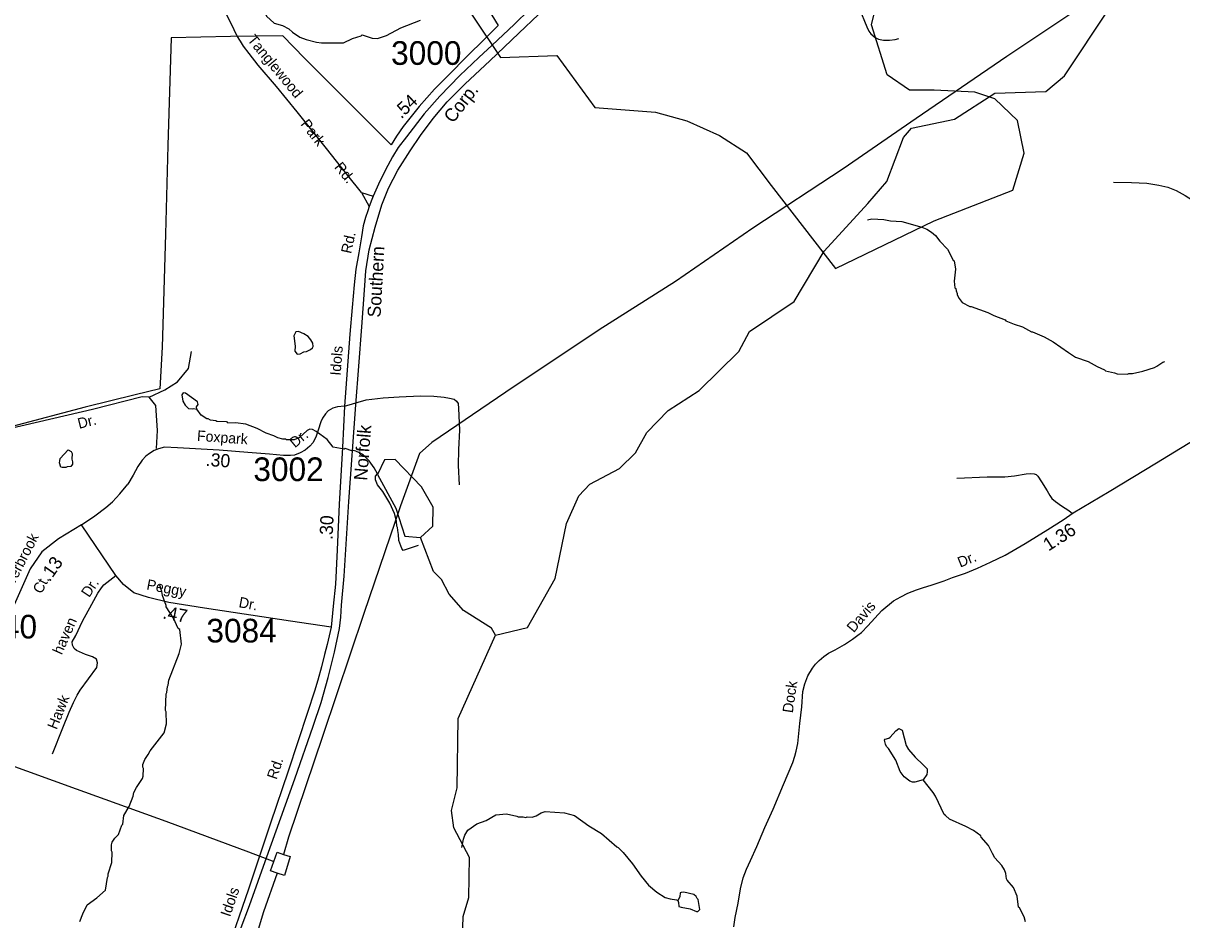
# Model space of a CAD drawing. Extents: x 1551653 to 1702041, y 811336 to 920032.
# Drawn here: x 1584838 to 1592068, y 814553 to 820151 of the extents above; entities that cross this region are included whole.
import ezdxf

# ---------------------------------------------------------------- set-up
doc = ezdxf.new("R2010")
doc.units = 0
for name, color, linetype in [('Old_Level_10', 7, 'Continuous'), ('Old_Level_11', 7, 'Continuous'), ('Old_Level_14', 7, 'Continuous'), ('Old_Level_17', 7, 'Continuous'), ('Old_Level_32', 7, 'Continuous'), ('Old_Level_35', 7, 'Continuous'), ('Old_Level_44', 7, 'Continuous'), ('Old_Level_48', 7, 'Continuous'), ('Old_Level_49', 7, 'Continuous'), ('Old_Level_53', 7, 'Continuous'), ('Old_Level_56', 7, 'Continuous'), ('Old_Level_59', 7, 'Continuous'), ('Old_Level_60', 7, 'Continuous'), ('Old_Level_62', 7, 'Continuous'), ('Old_Level_8', 7, 'Continuous')]:
    doc.layers.add(name, color=color, linetype=linetype)

msp = doc.modelspace()

# ---------------------------------------------------------------- linework, layer by layer
at = {"layer": 'Old_Level_32'}
for points in [[(1588000.194, 820239.075), (1587900.745, 820142.609), (1587764.879, 820014.729), (1587681.559, 819936.307), (1587563.41, 819824.135), (1587437.39, 819696.042), (1587339.631, 819585.756), (1587229.372, 819441.583), (1587178.112, 819374.343), (1587141.508, 819317.312), (1587099.805, 819235.764), (1587054.34, 819146.41), (1587021.295, 819070.925), (1587013.021, 819051.397), (1586996.374, 819007.418), (1586987.929, 818979.36), (1586973.296, 818937.638), (1586960.432, 818886.033), (1586949.212, 818818.31), (1586931.436, 818718.55), (1586913.907, 818614.846), (1586902.404, 818516.93), (1586890.048, 818377.012), (1586877.129, 818209.204), (1586859.799, 817985.681), (1586842.093, 817759.868)], [(1586842.093, 817759.868), (1586800.013, 817756.78), (1586769.947, 817747.213), (1586741.725, 817731.374), (1586723.609, 817712.043), (1586704.701, 817686.167), (1586694.373, 817662.41), (1586679.534, 817610.518), (1586664.862, 817566.83), (1586644.445, 817531.134), (1586626.286, 817509.835), (1586597.575, 817486.128), (1586567.346, 817468.356), (1586530.965, 817454.98), (1586504.964, 817451.564), (1586462.307, 817452.431), (1586375.141, 817459.776), (1586239.482, 817471.715), (1586061.5, 817484.511), (1585801.852, 817500.931), (1585719.854, 817504.232), (1585681.586, 817494.832), (1585655.418, 817483.215), (1585625.195, 817465.774), (1585603.151, 817447.181), (1585580.337, 817422.693), (1585553.932, 817383.182), (1585524.936, 817329.278), (1585490.009, 817274.18)], [(1586842.093, 817759.868), (1586829.976, 817502.099), (1586810.013, 817148.639), (1586797.66, 816862.973), (1586786.102, 816648.856), (1586771.824, 816511.274), (1586758.874, 816379.902)], [(1589272.456, 814509.499), (1589281.187, 814567.158), (1589298.649, 814658.014), (1589313.141, 814747.823), (1589330.602, 814815.965), (1589351.556, 814870.129), (1589376.002, 814924.293), (1589416.164, 815011.655), (1589466.803, 815130.468), (1589517.441, 815244.038), (1589582.049, 815397.447), (1589639.672, 815535.478), (1589653.641, 815575.664), (1589660.626, 815607.114), (1589671.103, 815654.29), (1589685.072, 815780.091), (1589697.295, 815883.178), (1589702.534, 815979.276), (1589714.978, 816025.949), (1589735.181, 816076.487), (1589762.599, 816124.136), (1589781.358, 816148.683), (1589804.446, 816173.23), (1589834.751, 816197.777), (1589863.611, 816217.992), (1589904.016, 816239.651), (1589963.181, 816272.862), (1590012.245, 816304.629), (1590046.879, 816330.619), (1590068.524, 816347.946), (1590108.929, 816388.377), (1590195.512, 816485.12), (1590269.108, 816544.321), (1590313.842, 816568.869), (1590358.577, 816593.416), (1590412.708, 816614.583), (1590448.656, 816625.374), (1590509.768, 816645.158), (1590585.259, 816670.337), (1590637.384, 816690.121), (1590718.268, 816717.099), (1590792.501, 816749.472), (1590874.643, 816787.241), (1590966.31, 816830.405), (1591090.332, 816902.346), (1591232.327, 816990.474), (1591327.59, 817051.623), (1591390.5, 817094.788), (1591614.457, 817228.418), (1591909.231, 817406.471), (1592220.184, 817595.316)], [(1585202.024, 817019.055), (1585058.115, 816932.179), (1584955.323, 816849.875), (1584882.227, 816744.71), (1584749.169, 816445.787)], [(1586758.874, 816379.902), (1586505.321, 816418.769), (1585968.519, 816498.786), (1585747.6, 816535.019), (1585619.681, 816564.74), (1585528.311, 816594.461), (1585464.352, 816647.044), (1585416.662, 816703.125), (1585202.024, 817019.055)], [(1586758.874, 816379.902), (1586733.818, 816271.757), (1586718.779, 816210.022), (1586699.809, 816132.279), (1586676.122, 816048.723), (1586655.052, 815980.872), (1586612.966, 815847.795), (1586490.984, 815481.627), (1586381.674, 815157.55), (1586243.016, 814745.766), (1586104.482, 814340.216), (1586122.37, 814330.733)]]:
    msp.add_lwpolyline(points, dxfattribs=at)
at = {"layer": 'Old_Level_35'}
for q in [(1586996.374, 819007.418), (1587021.295, 819070.925)]:
    msp.add_line((1586949.546, 819094.041), q, dxfattribs=at)
for points in [[(1589878.1, 820706.23), (1589973.779, 820454.813), (1590054.553, 820245.388), (1590102.739, 820128.537), (1590115.318, 820101.362), (1590127.453, 820084.705), (1590153.579, 820061.854), (1590175.363, 820051.566), (1590205.432, 820045.047), (1590243.493, 820044.276), (1590279.386, 820049.788), (1590301.489, 820055.247)], [(1586949.546, 819094.041), (1586863.385, 819199.517), (1586729.947, 819369.635), (1586547.812, 819598.837), (1586418.396, 819756.727), (1586304.538, 819888.695), (1586247.917, 819961.733), (1586212.419, 820008.078), (1586194.984, 820038.633), (1586171.756, 820074.883), (1586138.718, 820145.473), (1586090.044, 820238.045), (1586053.364, 820307.064), (1586014.174, 820365.633), (1585977.124, 820416.28), (1585937.527, 820454.829), (1585882.344, 820501.578), (1585838.725, 820535.941), (1585787.574, 820571.119), (1585740.946, 820602.92), (1585692.482, 820624.911), (1585652.653, 820635.564), (1585612.735, 820641.952), (1585558.791, 820652.893)], [(1591641.01, 819159.533), (1591754.875, 819157.555), (1591848.972, 819152.04), (1591924.576, 819140.987), (1591980.445, 819128.037), (1592032.217, 819107.296), (1592087.722, 819076.299), (1592135.35, 819045.462), (1592172.846, 819016.801), (1592208.381, 818988.507), (1592241.475, 818953.041), (1592260.294, 818926.069), (1592286.462, 818889.104), (1592323.965, 818828.271), (1592405.749, 818701.221), (1592516.789, 818527.291), (1592635.749, 818339.414), (1592780.266, 818116.878), (1592844.385, 818014.772)], [(1585623.94, 817815.733), (1585721.313, 817861.413), (1585800.43, 817913.183), (1585870.416, 817995.406), (1585888.674, 818101.992)], [(1585669.583, 817495.975), (1585675.669, 817608.652), (1585666.541, 817763.963), (1585623.94, 817815.733), (1585581.339, 817818.778), (1585270.961, 817739.6), (1584668.464, 817599.516), (1584333.744, 817532.519), (1584257.67, 817502.066), (1584187.683, 817480.749), (1584129.868, 817474.658), (1584084.224, 817474.658), (1584038.58, 817495.975), (1583980.765, 817559.927), (1583925.993, 817608.652), (1583865.134, 817623.879), (1583746.461, 817614.742), (1583646.044, 817572.108), (1583563.886, 817517.293)], [(1586842.093, 817759.868), (1586978.779, 817798.788), (1587084.746, 817812.072), (1587184.999, 817818.575), (1587317.069, 817824.106), (1587401.409, 817823.056), (1587464.946, 817815.858), (1587498.951, 817809.261), (1587526.763, 817804.759), (1587542.56, 817790.652), (1587552.445, 817776.337), (1587553.81, 817746.439), (1587559.581, 817610.094), (1587553.548, 817490.4), (1587551.848, 817390.315), (1587558.239, 817268.402)], [(1590663.109, 817311.538), (1590852.98, 817318.527), (1590963.279, 817318.589), (1591023.16, 817325.584), (1591097.281, 817338.527), (1591124.568, 817340.6), (1591147.484, 817337.51), (1591158.554, 817333.018), (1591169.19, 817323.284), (1591191.795, 817288.684), (1591227.747, 817232.48), (1591245.191, 817202.257), (1591257.615, 817183.622), (1591278.583, 817165.472), (1591317.418, 817138.094), (1591363.757, 817108.271), (1591384.855, 817090.915)], [(1585202.024, 817019.055), (1585284.763, 817075.473), (1585353.093, 817126.611), (1585396.183, 817163.488), (1585441.17, 817212.798), (1585490.009, 817274.18)], [(1585020.544, 815589.482), (1585085.205, 815751.316), (1585124.628, 815849.984), (1585151.764, 815909.505), (1585174.72, 815956.965), (1585193.05, 815986.795), (1585298.386, 816129.138), (1585302.329, 816158.724), (1585296.415, 816180.421), (1585270.788, 816196.201), (1585227.421, 816210.008), (1585170.255, 816235.651), (1585156.456, 816247.485), (1585146.6, 816267.21), (1585144.629, 816288.907), (1585166.501, 816329.051), (1585208.033, 816418.483), (1585265.638, 816523.673), (1585304.788, 816592.797), (1585327.466, 816626.478), (1585341.609, 816644.247), (1585359.982, 816659.959), (1585416.662, 816703.125)]]:
    msp.add_lwpolyline(points, dxfattribs=at)
at = {"layer": 'Old_Level_44'}
msp.add_lwpolyline([(1586146.536, 814367.479), (1586250.539, 814642.387), (1586357.566, 814947.383), (1586532.1, 815433.711), (1586647.214, 815762.559), (1586696.624, 815910.039), (1586740.193, 816065.639), (1586779.645, 816225.327), (1586811.249, 816372.964), (1586819.868, 816442.83), (1586824.609, 816518.771), (1586840.255, 816698.551), (1586870.692, 817164.183), (1586914.53, 817767.817), (1586932.834, 818009.578), (1586951.216, 818255.336), (1586967.473, 818485.129), (1586976.508, 818605.21), (1586997.752, 818735.25), (1587035.271, 818878.566), (1587076.479, 819016.207), (1587117.436, 819121.833), (1587176.718, 819233.096), (1587251.813, 819354.441), (1587316.777, 819449.779), (1587395.789, 819557.036), (1587482.721, 819660.133), (1587595.864, 819773.105), (1587749.227, 819915.477), (1587930.85, 820089.899), (1588054.036, 820204.666)], dxfattribs=at)
at = {"layer": 'Old_Level_48'}
msp.add_line((1589907.165, 818618.738), (1590523.491, 818917.763), dxfattribs=at)
for points in [[(1586598.583, 821757.824), (1587817.228, 819936.49), (1588167.412, 819950.081), (1588405.538, 819623.872), (1588783.738, 819596.688), (1588979.842, 819542.321), (1589182.97, 819449.856), (1589351.059, 819341.12), (1589505.14, 819137.239), (1589907.165, 818618.738)], [(1590523.491, 818917.763), (1591013.75, 819108.051), (1591083.787, 819339.116), (1591041.764, 819542.997), (1590901.691, 819678.917), (1590775.624, 819719.694), (1590523.491, 819733.286), (1590369.409, 819733.286), (1590229.336, 819828.43), (1590131.284, 820141.047), (1590229.336, 820548.809)]]:
    msp.add_lwpolyline(points, dxfattribs=at)
at = {"layer": 'Old_Level_49'}
msp.add_line((1589907.165, 818618.738), (1590523.491, 818917.763), dxfattribs=at)
for points in [[(1586598.583, 821757.824), (1587817.228, 819936.49), (1588167.412, 819950.081), (1588405.538, 819623.872), (1588783.738, 819596.688), (1588979.842, 819542.321), (1589182.97, 819449.856), (1589351.059, 819341.12), (1589505.14, 819137.239), (1589907.165, 818618.738)], [(1590523.491, 818917.763), (1591013.75, 819108.051), (1591083.787, 819339.116), (1591041.764, 819542.997), (1590901.691, 819678.917), (1590775.624, 819719.694), (1590523.491, 819733.286), (1590369.409, 819733.286), (1590229.336, 819828.43), (1590131.284, 820141.047), (1590229.336, 820548.809)]]:
    msp.add_lwpolyline(points, dxfattribs=at)
at = {"layer": 'Old_Level_53'}
msp.add_lwpolyline([(1587437.823, 820733.812), (1587802.33, 820136.723), (1587714.699, 820048.449), (1587610.582, 819946.5), (1587490.257, 819824.867), (1587404.467, 819738.558), (1587308.427, 819630.441), (1587210.064, 819506.367), (1587166.806, 819445.209), (1587133.709, 819391.849), (1586825.58, 819699.847), (1586593.963, 819932.255), (1586458.737, 820072.865), (1586132.455, 820067.261), (1585762.321, 820060.342), (1585741.281, 819386.81), (1585726.468, 818833.215), (1585704.782, 818127.679), (1585689.716, 817867.846), (1585537.089, 817830.914), (1585225.39, 817754.979), (1584769.098, 817633.743)], dxfattribs=at)
at = {"layer": 'Old_Level_56'}
for points in [[(1591487.044, 820284.472), (1590975.887, 819944.03), (1590410.33, 819555.461), (1589955.344, 819241.699), (1589391.95, 818871.096), (1588908.758, 818538.091), (1588432.001, 818236.176), (1587850.437, 817847.732), (1587387.449, 817534.13), (1587310.415, 817465.249), (1587191.731, 817138.078), (1586963.414, 816466.137), (1586708.274, 815704.691), (1586492.523, 815070.319), (1586461.312, 814961.891)], [(1579362.998, 819590.988), (1580225.931, 818651.979), (1580861.501, 817971.96), (1581222.199, 817572.053), (1581605.997, 817156.867), (1581926.292, 816807.406), (1582195.842, 816511.396), (1582350.668, 816340.573), (1582649.45, 816243.076), (1582831.398, 816176.56), (1583442.926, 815969.481), (1584198.479, 815710.462), (1584714.81, 815535.525), (1585169.324, 815371.244), (1585727.344, 815170.05), (1586244.515, 814977.485), (1586401.585, 814917.478)], [(1586401.585, 814917.478), (1586422.572, 814975.684), (1586461.312, 814961.891)], [(1586423.734, 814845.192), (1586382.182, 814858.637), (1586401.585, 814917.478)], [(1586461.312, 814961.891), (1586504.055, 814948.02), (1586467.661, 814830.694), (1586423.734, 814845.192)], [(1586423.734, 814845.192), (1586338.012, 814604.195), (1586259.446, 814341.046), (1586181.769, 814131.706), (1586135.627, 813967.752), (1586039.896, 813519.049), (1585998.964, 813266.543), (1585923.207, 812786.219), (1585896.365, 812574.246)]]:
    msp.add_lwpolyline(points, dxfattribs=at)
at = {"layer": 'Old_Level_59'}
for points in [[(1587784.514, 816330.594), (1587985.567, 816379.038), (1588156.581, 816684.155), (1588227.529, 817027.361), (1588305.551, 817199.759), (1588373.526, 817273.885), (1588558.585, 817371.9), (1588659.573, 817468.325), (1588728.573, 817594.997), (1588863.6, 817733.355), (1589056.554, 817857.463), (1589302.617, 818101.988), (1589370.591, 818225.378), (1589648.54, 818413.36), (1589836.572, 818728.012), (1590107.549, 819024.517), (1590226.581, 819163.286), (1590330.543, 819436.877), (1590381.601, 819494.958), (1590648.579, 819551.911), (1590901.613, 819714.158), (1591218.623, 819724.155), (1591336.631, 819823.554), (1591617.552, 820244.628)], [(1587784.514, 816330.594), (1587759.6, 816373.757), (1587586.536, 816485.562), (1587496.518, 816585.884), (1587447.613, 816678.772), (1587398.606, 816729.01), (1587317.61, 816940.778)], [(1586965.238, 812210.855), (1586967.288, 812335.526), (1586945.543, 812565.992), (1587022.54, 812699.019), (1587199.603, 812770.941), (1587234.564, 812914.683), (1587403.527, 813062.269), (1587480.524, 813218.263), (1587483.6, 813402.04), (1587451.509, 813468.324), (1587465.555, 813861.972), (1587568.594, 814099.474), (1587583.563, 814575.143), (1587618.524, 814692.587), (1587622.522, 814942.033), (1587525.533, 815127.861), (1587510.564, 815236.488), (1587545.525, 815376.948), (1587551.574, 815810.069), (1587784.514, 816330.594)]]:
    msp.add_lwpolyline(points, dxfattribs=at)
at = {"layer": 'Old_Level_60'}
msp.add_lwpolyline([(1587317.61, 816940.778), (1587394.607, 817011.418), (1587395.53, 817129.579), (1587322.531, 817255.789), (1587158.592, 817426.546), (1587091.54, 817424.598), (1587048.582, 817333.504), (1587162.591, 817124.453), (1587218.57, 816949.339), (1587317.61, 816940.778)], dxfattribs=at)
at = {"layer": 'Old_Level_62'}
for points in [[(1586118.465, 820508.633), (1586159.476, 820436.403), (1586210.534, 820363.148), (1586242.112, 820332.955), (1586269.896, 820316.806), (1586323.21, 820273.848), (1586356.121, 820195.21), (1586403.59, 820150.766), (1586455.468, 820137.437), (1586495.044, 820115.292), (1586518.83, 820095.094), (1586564.351, 820063.824), (1586604.029, 820049.88), (1586667.902, 820033.014), (1586699.788, 820028.247), (1586835.84, 820027.94), (1586892.434, 820055.519), (1586946.773, 820072.487), (1586952.822, 820078.126), (1587016.388, 820057.928), (1587048.377, 820054.852), (1587104.766, 820074.23), (1587195.399, 820123.237), (1587316.175, 820170.861)], [(1590107.344, 818924.4), (1590133.488, 818929.578), (1590209.357, 818926.4), (1590249.445, 818918.198), (1590321.315, 818913.482), (1590444.654, 818877.341), (1590476.642, 818865.192), (1590506.477, 818846.532), (1590530.058, 818826.385), (1590557.638, 818789.681), (1590604.8, 818741.135), (1590641.812, 818672.289), (1590647.861, 818668.034), (1590655.038, 818614.567), (1590647.963, 818540.03), (1590651.449, 818498.097), (1590657.293, 818493.893), (1590659.036, 818479.899), (1590666.931, 818464.161), (1590666.726, 818455.959), (1590678.414, 818431.917), (1590697.996, 818407.721), (1590745.671, 818382.96), (1590753.668, 818382.807), (1590857.219, 818345.385), (1590894.949, 818326.571), (1590964.564, 818299.709), (1590970.613, 818293.865), (1591022.286, 818272.284), (1591074.062, 818255.675), (1591129.631, 818223.379), (1591135.577, 818224.865), (1591209.191, 818193.851), (1591264.76, 818161.504), (1591359.904, 818095.58), (1591405.426, 818065.129), (1591483.038, 818038.114), (1591538.607, 818007.459), (1591586.384, 817986.8), (1591592.228, 817980.085), (1591648.207, 817969.114), (1591664.099, 817961.425), (1591728.075, 817960.092), (1591736.175, 817964.039), (1591760.166, 817963.578), (1591824.245, 817978.7), (1591896.731, 818001.82), (1591912.93, 818009.715), (1591949.121, 818035.244), (1591961.322, 818039.088)], [(1586547.639, 818085.532), (1586565.684, 818086.814), (1586589.778, 818098.655), (1586605.874, 818102.449), (1586630.07, 818114.239), (1586644.219, 818123.826), (1586648.32, 818131.926), (1586644.629, 818154.174), (1586632.941, 818174.115), (1586615.307, 818194.159), (1586589.368, 818212.716), (1586555.636, 818227.377), (1586539.54, 818223.584), (1586527.237, 818200.054), (1586534.311, 818135.872), (1586533.901, 818103.884), (1586547.639, 818085.532)], [(1585920.488, 817740.481), (1585918.54, 817756.065), (1585928.895, 817770.675), (1585925.101, 817786.31), (1585851.693, 817841.162), (1585835.801, 817843.93), (1585827.702, 817831.78), (1585835.083, 817791.437), (1585848.822, 817767.343), (1585862.355, 817751.502), (1585870.455, 817744.736), (1585894.446, 817742.634), (1585902.546, 817746.581), (1585920.488, 817740.481)], [(1587049.094, 817337.656), (1587027.461, 817375.847), (1586996.191, 817418.293), (1586960.717, 817453.511), (1586936.828, 817469.556), (1586913.042, 817479.911), (1586897.151, 817484.319), (1586889.154, 817482.013), (1586847.118, 817495.187), (1586841.069, 817492.829), (1586773.197, 817504.056), (1586734.032, 817552.448), (1586666.672, 817601.404), (1586642.886, 817614.22), (1586626.995, 817616.168), (1586610.795, 817608.325), (1586562.096, 817564.957), (1586529.8, 817549.218), (1586481.818, 817550.193), (1586473.923, 817554.447), (1586457.929, 817554.755), (1586426.044, 817562.804), (1586402.155, 817575.619), (1586354.48, 817592.177), (1586298.809, 817621.192), (1586227.143, 817648.054), (1586163.269, 817656.768), (1586115.185, 817653.642), (1586113.339, 817659.434), (1586107.393, 817661.997), (1586047.312, 817664.868), (1586039.418, 817668.303), (1586007.532, 817673.019), (1585991.436, 817681.58), (1585983.439, 817681.734), (1585947.76, 817703.777), (1585920.488, 817740.481)], [(1585067.266, 817418.805), (1585069.624, 817434.338), (1585118.324, 817487.549), (1585138.214, 817477.297), (1585144.058, 817465.66), (1585141.495, 817429.622), (1585145.288, 817413.116), (1585144.981, 817397.532), (1585134.831, 817383.793), (1585112.89, 817381.793), (1585104.79, 817377.847), (1585080.697, 817376.667), (1585072.802, 817378.462), (1585065.113, 817406.554), (1585067.266, 817418.805)], [(1587302.641, 816890.181), (1587210.06, 816859.218), (1587200.32, 816871.726), (1587182.993, 816922.118), (1587179.507, 816961.591), (1587177.662, 816969.844), (1587174.176, 817001.934), (1587170.28, 817010.188), (1587166.794, 817042.279), (1587155.516, 817090.107), (1587126.399, 817154.698), (1587081.493, 817227.031), (1587048.069, 817269.527), (1587036.381, 817300.132), (1587036.894, 817323.918), (1587049.094, 817337.656)], [(1585191.733, 814543.207), (1585210.392, 814591.24), (1585237.152, 814647.321), (1585297.949, 814690.382), (1585350.648, 814737.749), (1585363.669, 814817.104), (1585367.77, 814825.204), (1585368.077, 814840.788), (1585391.043, 814910.916), (1585392.171, 814974.892), (1585388.172, 814983.197), (1585388.788, 815022.567), (1585392.991, 815038.868), (1585409.293, 815062.347), (1585431.746, 815086.492), (1585454.404, 815144.317), (1585460.556, 815149.956), (1585465.375, 815205.627), (1585498.285, 815261.607), (1585523.199, 815325.121), (1585527.505, 815348.805), (1585546.063, 815380.434), (1585582.767, 815434.721), (1585587.073, 815450.203), (1585587.791, 815498.595), (1585583.895, 815506.079), (1585583.997, 815522.484), (1585596.505, 815554.216), (1585618.856, 815585.794), (1585631.262, 815609.323), (1585717.076, 815720.872), (1585731.942, 815776.338), (1585731.019, 815852.669), (1585727.021, 815860.154), (1585730.609, 815964.32), (1585734.608, 815972.42), (1585739.119, 816010.097), (1585743.425, 816018.197), (1585747.731, 816050.134), (1585812.22, 816217.047), (1585825.036, 816273.436), (1585814.476, 816365.555), (1585804.531, 816371.502), (1585775.516, 816437.734), (1585730.507, 816506.734), (1585730.507, 816514.987), (1585707.336, 816578.604), (1585703.748, 816603.313), (1585690.419, 816642.991)], [(1590454.804, 815427.955), (1590402.619, 815412.576), (1590386.625, 815412.883), (1590370.528, 815418.984), (1590334.951, 815445.128), (1590309.422, 815480.14), (1590282.458, 815550.422), (1590237.654, 815622.703), (1590225.761, 815635.262), (1590217.867, 815651.051), (1590212.228, 815674.94), (1590216.431, 815681.399), (1590240.525, 815686.679), (1590248.419, 815693.087), (1590283.176, 815734.252), (1590301.323, 815747.836), (1590323.263, 815737.532), (1590347.767, 815641.004), (1590361.403, 815616.91), (1590402.926, 815568.518), (1590454.087, 815521.51), (1590477.77, 815495.571), (1590479.411, 815477.475), (1590477.258, 815461.122), (1590454.804, 815427.955)], [(1591092.106, 814540.233), (1591084.519, 814572.375), (1591055.299, 814628.764), (1591049.455, 814632.968), (1591040.433, 814701.302), (1591017.262, 814755.076), (1590977.995, 814801.828), (1590974.099, 814810.133), (1590970.408, 814842.223), (1590960.873, 814866.214), (1590945.186, 814891.948), (1590901.818, 814941.263), (1590886.336, 814966.998), (1590860.91, 815017.595), (1590815.593, 815070.19), (1590813.953, 815078.443), (1590768.226, 815111.354), (1590720.757, 815135.294), (1590617.206, 815180.919), (1590593.522, 815205.166), (1590585.628, 815211.932), (1590531.289, 815324.608), (1590515.602, 815348.754), (1590454.804, 815427.955)], [(1587575.463, 815005.342), (1587586.126, 815056.81), (1587594.43, 815081.263), (1587612.885, 815112.944), (1587669.479, 815152.006), (1587725.971, 815173.024), (1587786.359, 815207.883), (1587854.641, 815215.521), (1587918.31, 815200.296), (1587926.205, 815196.041), (1587958.193, 815195.375), (1587974.392, 815191.786), (1587982.286, 815195.733), (1588014.479, 815195.067), (1588038.368, 815202.757), (1588070.766, 815221.826), (1588094.962, 815229.516), (1588214.815, 815222.185), (1588278.689, 815205.32), (1588367.579, 815139.498), (1588447.139, 815092.746), (1588541.873, 815009.598), (1588549.768, 815005.291), (1588581.346, 814972.688), (1588640.401, 814903.381), (1588693.202, 814826.794), (1588740.466, 814770.045), (1588791.934, 814725.498), (1588843.403, 814692.433), (1588875.186, 814684.436), (1588915.273, 814677.874), (1588923.168, 814673.568)], [(1588923.168, 814673.568), (1588927.064, 814661.214), (1588928.602, 814637.376), (1588944.493, 814632.968), (1589000.575, 814622.767), (1589040.15, 814605.593), (1589048.147, 814605.388), (1589060.348, 814617.486), (1589049.275, 814680.079), (1589043.431, 814685.923), (1589037.587, 814700.02), (1589021.798, 814711.81), (1588959.975, 814725.395), (1588943.981, 814724.883), (1588937.932, 814721.704), (1588935.573, 814697.149), (1588923.168, 814673.568)]]:
    msp.add_lwpolyline(points, dxfattribs=at)

# ---------------------------------------------------------------- texts
at = {"layer": 'Old_Level_10'}
for s, rotation, p in [('Tanglewood', 309.5838417, (1586233.073, 820045.909)), ('Park', 307.7836417, (1586565.693, 819520.099)), ('Rd.', 309.3400056, (1586775.773, 819250.678)), ('Dr.', 13.9682167, (1585186.856, 817618.412)), ('Dr.', 56.0479944, (1585249.383, 816561.596)), ('haven', 66.2514667, (1585078.664, 816204.358)), ('Hawk', 68.2209306, (1585046.882, 815737.017))]:
    msp.add_text(s, height=65.6167, rotation=rotation, dxfattribs=at).set_placement(p)
at = {"layer": 'Old_Level_11'}
for s, rotation, p in [('Rd.', 77.6330667, (1586884.222, 818708.743)), ('Idols', 85.3337917, (1586817.977, 817949.319)), ('Foxpark', 355.8880389, (1585921.07, 817544.034)), ('Dr.', 39.5476528, (1586533.351, 817496.755)), ('Riverbrook', 62.7771389, (1584742.933, 816567.991)), ('Dr.', 22.0094444, (1590684.913, 816751.826)), ('Ct.', 62.2731778, (1584952.015, 816583.99)), ('Peggy', 349.1562778, (1585604.07, 816616.175)), ('Dr.', 349.3686306, (1586179.447, 816505.905)), ('Davis', 49.8242139, (1590020.521, 816342.077)), ('Dock', 81.7140278, (1589640, 815841.994)), ('Rd.', 71.3608306, (1586419.15, 815425.385)), ('Idols', 71.1401889, (1586128.766, 814568.033))]:
    msp.add_text(s, height=65.6167, rotation=rotation, dxfattribs=at).set_placement(p)
at = {"layer": 'Old_Level_14'}
for s, rotation, p in [('Corp.', 52.3466222, (1587520.293, 819522.12)), ('Southern', 86.8019806, (1587067.642, 818312.238)), ('Norfolk', 85.5560139, (1586983.543, 817293.449))]:
    msp.add_text(s, height=82.0208, rotation=rotation, dxfattribs=at).set_placement(p)
at = {"layer": 'Old_Level_17'}
for s, rotation, p in [('.54', 44.0572361, (1587196.972, 819550.196)), ('.30', 355.8880222, (1585975.026, 817387.885)), ('.30', 87.5240389, (1586768.515, 816924.52)), ('1.36', 32.6968139, (1591235.811, 816852.251)), ('.13', 55.1984417, (1585003.009, 816659.529)), ('.47', 349.3686306, (1585704.371, 816435.41))]:
    msp.add_text(s, height=82.0208, rotation=rotation, dxfattribs=at).set_placement(p)
at = {"layer": 'Old_Level_8'}
for s, p in [('3000', (1587133.642, 819891.117)), ('3002', (1586274.138, 817292.597)), ('3140', (1584485.614, 816309.857)), ('3084', (1585981.013, 816285.022))]:
    msp.add_text(s, height=147.6375, dxfattribs=at).set_placement(p)

doc.saveas('drawing.dxf')
